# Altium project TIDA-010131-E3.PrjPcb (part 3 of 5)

## Sheet TIDA-010131-E3_LMX2594R_1.SchDoc: LMX2594R
size 431 x 279 mm; Date: Not shown in title block; ApprovedBy: Not shown in title block; CheckedBy: Not shown in title block; Author: Not shown in title block; CompanyName: Not shown in title block; DrawnBy: Avinash N; Engineer: Not shown in title block; Organization: Not shown in title block; Address1: Not shown in title block; Address2: Not shown in title block; Address3: Not shown in title block; Address4: Not shown in title block; DocumentNumber: 1; Revision: Use project parameter SCH_Rev; SheetNumber: 5; SheetTotal: 9; PageSetup: Record=PageOptions¦CenterHorizontal=True¦CenterVertical=True¦PrintScale=1.00¦XCorrection=1.00¦YCorrection=1.00¦PrintKind=0¦BorderSize=5000000¦LeftOffset=0¦BottomOffset=0¦Orientation=2¦PaperLength=1000¦PaperWidth=1000¦Scale=100¦PaperSource=15¦PrintQuality=600¦MediaType=1¦DitherType=10¦PaperKind=Letter¦PrintScaleMode=1
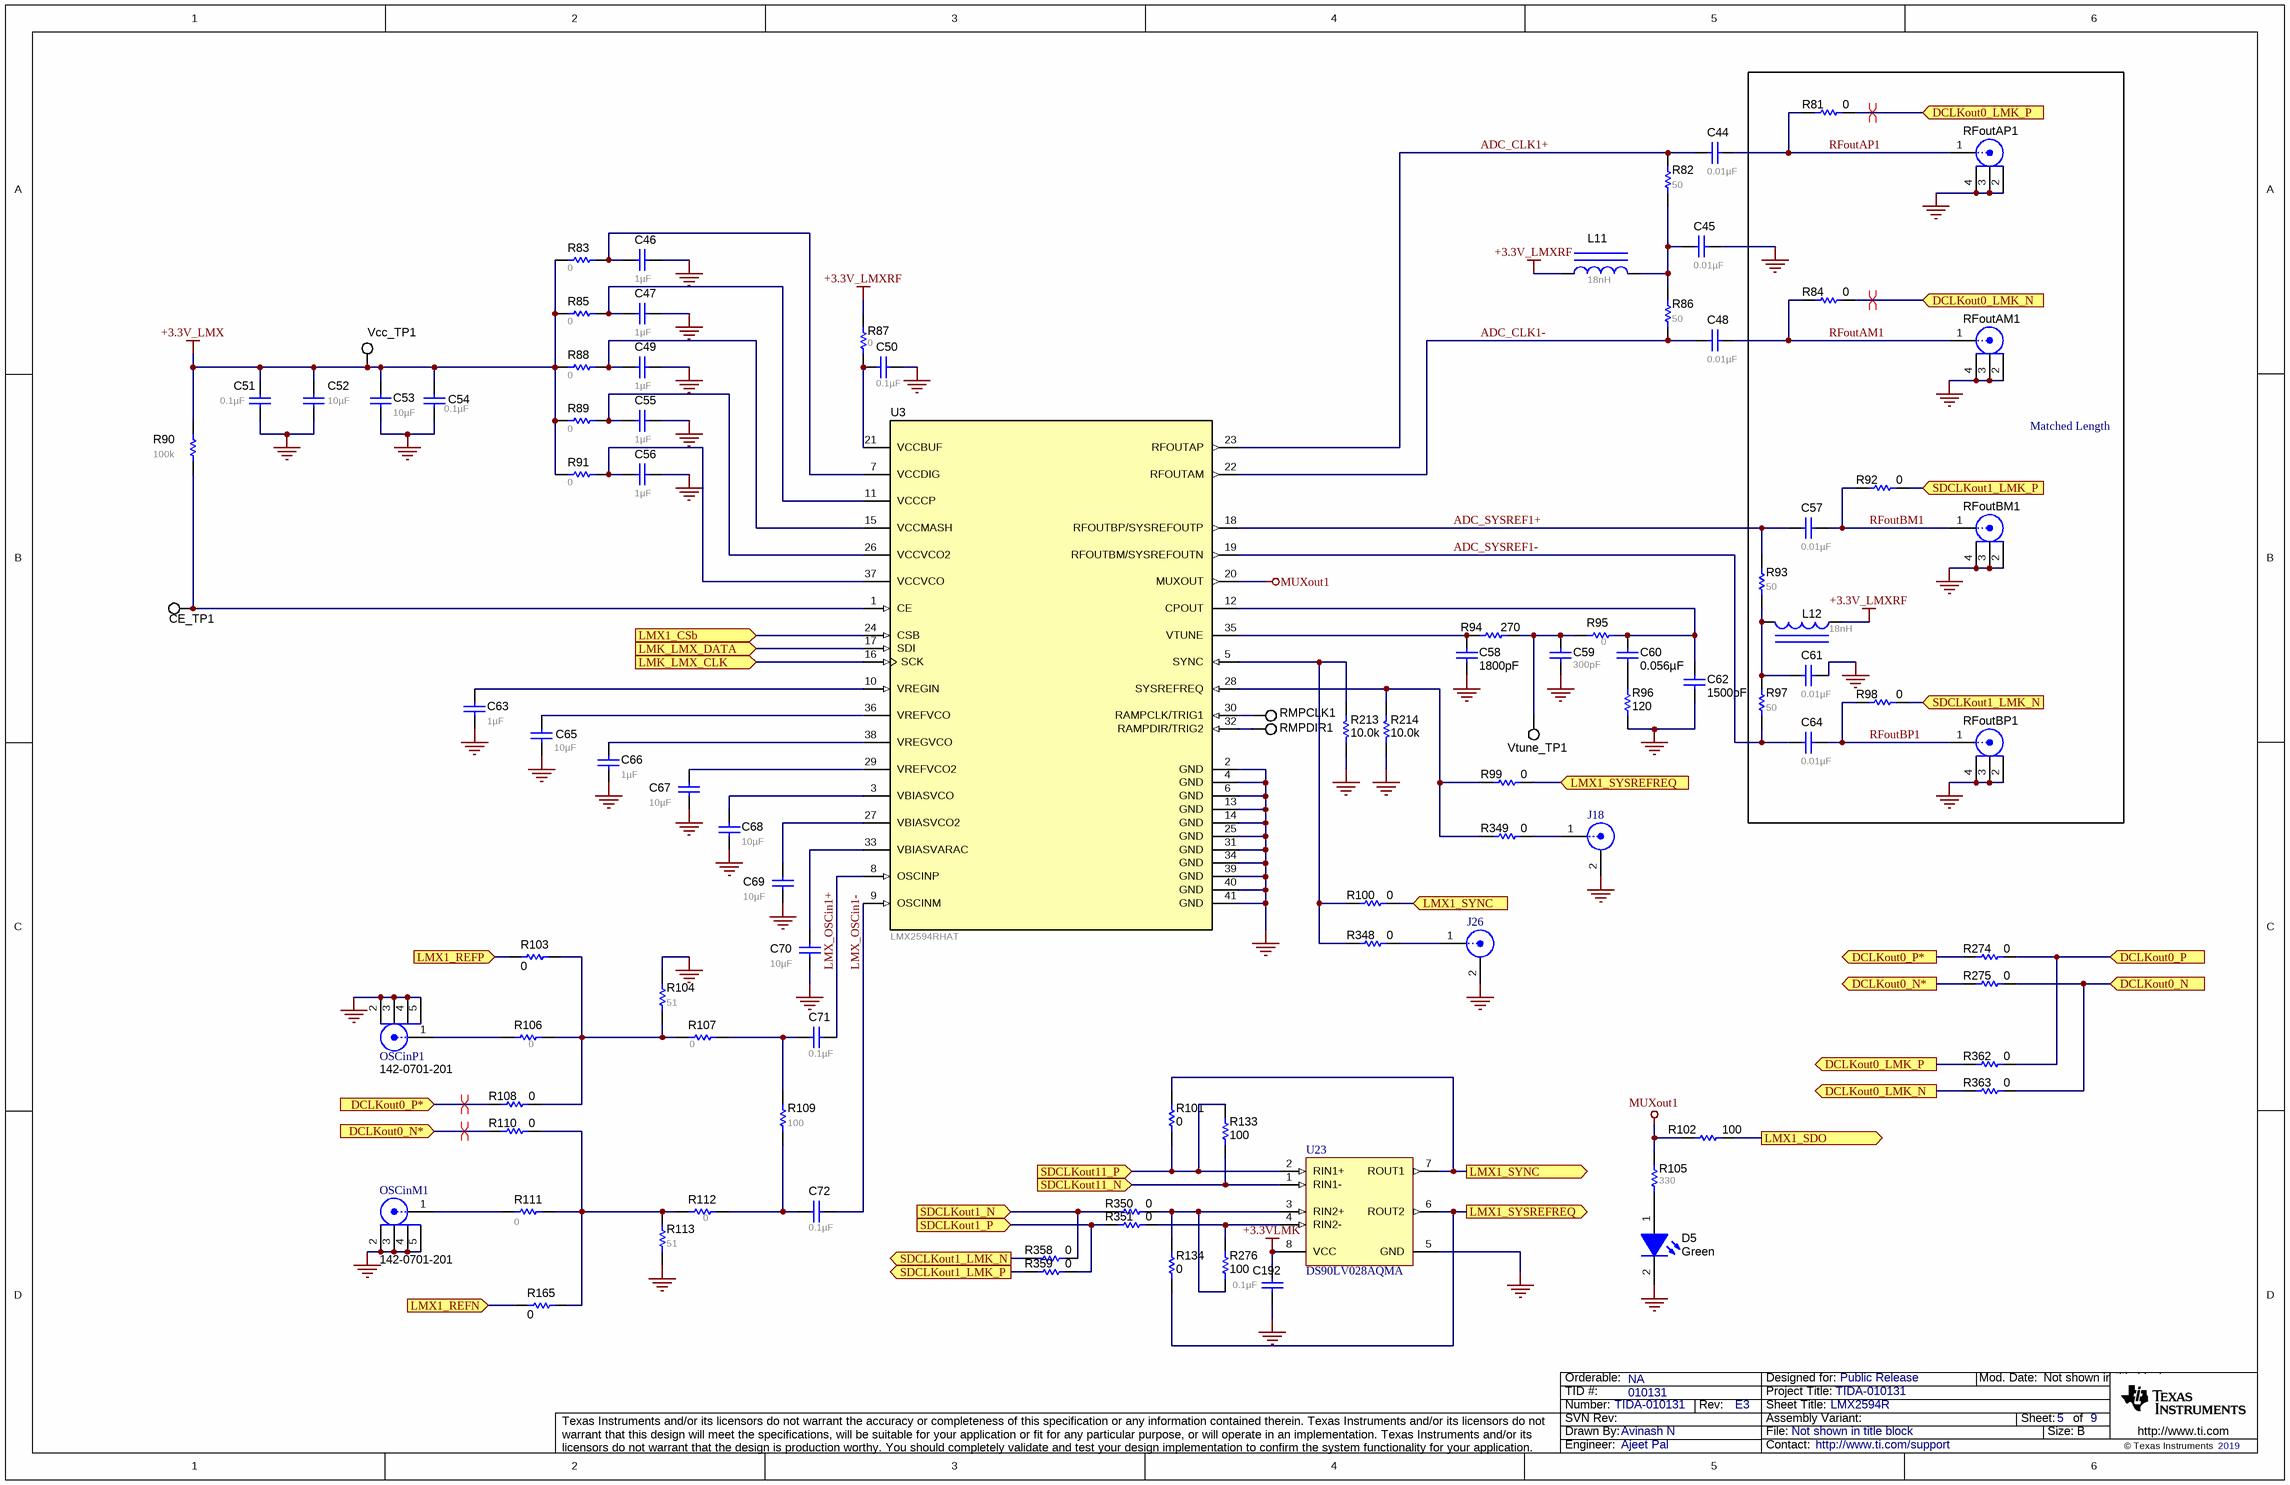
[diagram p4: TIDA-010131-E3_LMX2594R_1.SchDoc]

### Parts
C44  ValueDisplayed: 0.01µF  [0402_065]  (hidden comment: 520L103KT16T)
C45  ValueDisplayed: 0.01µF  [0402_065]  (hidden comment: 520L103KT16T)
C46  ValueDisplayed: 1µF  [0603]  (hidden comment: C1608X7R1C105K080AC)
C47  ValueDisplayed: 1µF  [0603L]  (hidden comment: C1608X7R1C105K080AC)
C48  ValueDisplayed: 0.01µF  [0402_065]  (hidden comment: 520L103KT16T)
C49  ValueDisplayed: 1µF  [0603L]  (hidden comment: C1608X7R1C105K080AC)
C50  ValueDisplayed: 0.1µF  [0603L]  (hidden comment: 0603YC104JAT2A)
C51  ValueDisplayed: 0.1µF  [0603]  (hidden comment: 0603YC104JAT2A)
C52  ValueDisplayed: 10µF  [0805]  (hidden comment: C0805C106K8PACTU)
C53  ValueDisplayed: 10µF  [0805]  (hidden comment: C0805C106K8PACTU)
C54  ValueDisplayed: 0.1µF  [0603]  (hidden comment: 0603YC104JAT2A)
C55  ValueDisplayed: 1µF  [0603]  (hidden comment: C1608X7R1C105K080AC)
C56  ValueDisplayed: 1µF  [0603]  (hidden comment: C1608X7R1C105K080AC)
C57  ValueDisplayed: 0.01µF  [0402_065]  (hidden comment: 520L103KT16T)
C58  ValueDisplayed: 1800pF  [0603]  (hidden comment: GRM1885C1H182JA01D)
C59  ValueDisplayed: 300pF  [0603]  (hidden comment: GRM1885C2A301JA01D)
C60  ValueDisplayed: 0.056µF  [0603]  (hidden comment: GRM188R71H563KA93D)
C61  ValueDisplayed: 0.01µF  [0402_065]  (hidden comment: 520L103KT16T)
C62  ValueDisplayed: 1500pF  [0603]  (hidden comment: GRM1885C1H152JA01J)
C63  ValueDisplayed: 1µF  [0603]  (hidden comment: C1608X7R1C105K080AC)
C64  ValueDisplayed: 0.01µF  [0402_065]  (hidden comment: 520L103KT16T)
C65  ValueDisplayed: 10µF  [0603]  (hidden comment: C1608X5R1A106M080AC)
C66  ValueDisplayed: 1µF  [0603]  (hidden comment: C1608X7R1C105K080AC)
C67  ValueDisplayed: 10µF  [0603]  (hidden comment: C1608X5R1A106M080AC)
C68  ValueDisplayed: 10µF  [0603]  (hidden comment: C1608X5R1A106M080AC)
C69  ValueDisplayed: 10µF  [0603]  (hidden comment: C1608X5R1A106M080AC)
C70  ValueDisplayed: 10µF  [0603]  (hidden comment: C1608X5R1A106M080AC)
C71  ValueDisplayed: 0.1µF  [0603L]  (hidden comment: 0603YC104JAT2A)
C72  ValueDisplayed: 0.1µF  [0603L]  (hidden comment: 0603YC104JAT2A)
C192  ValueDisplayed: 0.1µF  [0603]  (hidden comment: 0603YC104JAT2A)
CE_TP1  5007  [Keystone5007]  (value not drawn)
D5  value Green  [LTST-C191_Green]  (hidden comment: LTST-C191TGKT)
J18  (no value)  [Molex_0853050232]
J26  (no value)  [Molex_0853050232]
L11  ValueDisplayed: 18nH  [IND_LQG15H]  (hidden comment: LQG15HS18NJ02D)
L12  ValueDisplayed: 18nH  [IND_LQG15H]  (hidden comment: LQG15HS18NJ02D)
OSCinM1  142-0701-201  [Johnson_142-0701-20x]
OSCinP1  142-0701-201  [Johnson_142-0701-20x]
R81  ValueDisplayed: 0  [0402]  (hidden comment: CRCW04020000Z0ED)
R82  ValueDisplayed: 50  [0402L]  (hidden comment: FC0402E50R0BST1)
R83  value 0  [0603]  (hidden comment: CRCW06030000Z0EA)
R84  ValueDisplayed: 0  [0402]  (hidden comment: CRCW04020000Z0ED)
R85  value 0  [0603L]  (hidden comment: CRCW06030000Z0EA)
R86  ValueDisplayed: 50  [0402L]  (hidden comment: FC0402E50R0BST1)
R87  value 0  [0603L]  (hidden comment: CRCW06030000Z0EA)
R88  value 0  [0603L]  (hidden comment: CRCW06030000Z0EA)
R89  value 0  [0603]  (hidden comment: CRCW06030000Z0EA)
R90  ValueDisplayed: 100k  [0603]  (hidden comment: CRCW0603100KJNEA)
R91  value 0  [0603]  (hidden comment: CRCW06030000Z0EA)
R92  ValueDisplayed: 0  [0402]  (hidden comment: CRCW04020000Z0ED)
R93  ValueDisplayed: 50  [0402L]  (hidden comment: FC0402E50R0BST1)
R94  ValueDisplayed: 270  [0603]  (hidden comment: RC0603JR-07270RL)
R95  ValueDisplayed: 0  [0603]  (hidden comment: CRCW06030000Z0EA)
R96  ValueDisplayed: 120  [0603]  (hidden comment: CRCW0603120RJNEA)
R97  ValueDisplayed: 50  [0402L]  (hidden comment: FC0402E50R0BST1)
R98  ValueDisplayed: 0  [0402]  (hidden comment: CRCW04020000Z0ED)
R99  ValueDisplayed: 0  [0402]  (hidden comment: CRCW04020000Z0ED)
R100  ValueDisplayed: 0  [0402]  (hidden comment: CRCW04020000Z0ED)
R101  ValueDisplayed: 0  [0402]  (hidden comment: CRCW04020000Z0ED)
R102  ValueDisplayed: 100  [0603]  (hidden comment: CRCW0603100RFKEA)
R103  ValueDisplayed: 0  [0402]  (hidden comment: CRCW04020000Z0ED)
R104  ValueDisplayed: 51  [0603]  (hidden comment: CRCW060351R0JNEA)
R105  value 330  [0603]  (hidden comment: RC0603JR-07330RL)
R106  ValueDisplayed: 0  [0603]  (hidden comment: CRCW06030000Z0EA)
R107  ValueDisplayed: 0  [0603]  (hidden comment: CRCW06030000Z0EA)
R108  ValueDisplayed: 0  [0402]  (hidden comment: CRCW04020000Z0ED)
R109  ValueDisplayed: 100  [0603L]  (hidden comment: CRCW0603100RFKEA)
R110  ValueDisplayed: 0  [0402]  (hidden comment: CRCW04020000Z0ED)
R111  ValueDisplayed: 0  [0603]  (hidden comment: CRCW06030000Z0EA)
R112  ValueDisplayed: 0  [0603]  (hidden comment: CRCW06030000Z0EA)
R113  ValueDisplayed: 51  [0603]  (hidden comment: CRCW060351R0JNEA)
R133  ValueDisplayed: 100  [0402]  (hidden comment: CRCW0402100RJNED)
R134  ValueDisplayed: 0  [0402]  (hidden comment: CRCW04020000Z0ED)
R165  ValueDisplayed: 0  [0402]  (hidden comment: CRCW04020000Z0ED)
R213  ValueDisplayed: 10.0k  [0402]  (hidden comment: CRCW040210K0DHEDP)
R214  ValueDisplayed: 10.0k  [0402]  (hidden comment: CRCW040210K0DHEDP)
R274  ValueDisplayed: 0  [0402]  (hidden comment: CRCW04020000Z0ED)
R275  ValueDisplayed: 0  [0402]  (hidden comment: CRCW04020000Z0ED)
R276  ValueDisplayed: 100  [0402]  (hidden comment: CRCW0402100RJNED)
R348  ValueDisplayed: 0  [0402]  (hidden comment: CRCW04020000Z0ED)
R349  ValueDisplayed: 0  [0402]  (hidden comment: CRCW04020000Z0ED)
R350  ValueDisplayed: 0  [0402]  (hidden comment: CRCW04020000Z0ED)
R351  ValueDisplayed: 0  [0402]  (hidden comment: CRCW04020000Z0ED)
R358  ValueDisplayed: 0  [0402]  (hidden comment: CRCW04020000Z0ED)
R359  ValueDisplayed: 0  [0402]  (hidden comment: CRCW04020000Z0ED)
R362  ValueDisplayed: 0  [0402]  (hidden comment: CRCW04020000Z0ED)
R363  ValueDisplayed: 0  [0402]  (hidden comment: CRCW04020000Z0ED)
RFoutAM1  142-0771-831  [Johnson_142-0771-831]  (value not drawn)
RFoutAP1  142-0771-831  [Johnson_142-0771-831]  (value not drawn)
RFoutBM1  142-0771-831  [Johnson_142-0771-831]  (value not drawn)
RFoutBP1  142-0771-831  [Johnson_142-0771-831]  (value not drawn)
RMPCLK1  5007  [Keystone5007]  (value not drawn)
RMPDIR1  5007  [Keystone5007]  (value not drawn)
U3  LMX2594RHAT  [RHA0040A]
U23  DS90LV028AQMA  [M08A_N]
Vcc_TP1  5007  [Keystone5007]  (value not drawn)
Vtune_TP1  5007  [Keystone5007]  (value not drawn)

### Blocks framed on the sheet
Matched Length: C57 C61 C64 L12 R81 R84 R92 R93 R97 R98 RFoutAM1 RFoutAP1 RFoutBM1 RFoutBP1

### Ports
DCLKout0_LMK_N (in), DCLKout0_LMK_N (out), DCLKout0_LMK_P (in), DCLKout0_LMK_P (out), DCLKout0_N (in), DCLKout0_N* (in), DCLKout0_N* (out), DCLKout0_P (in), DCLKout0_P* (in), DCLKout0_P* (out), LMK_LMX_CLK (in), LMK_LMX_DATA (in), LMX1_CSb (in), LMX1_REFN (in), LMX1_REFP (in), LMX1_SDO (out), LMX1_SYNC (in), LMX1_SYNC (out), LMX1_SYSREFREQ (in), LMX1_SYSREFREQ (out), SDCLKout1_LMK_N (in), SDCLKout1_LMK_N (out), SDCLKout1_LMK_P (in), SDCLKout1_LMK_P (out), SDCLKout1_N (in), SDCLKout1_P (in), SDCLKout11_N (in), SDCLKout11_P (in)

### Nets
+3.3V_LMX: C51.2 C52.2 C53.2 C54.2 R83.1 R85.1 R88.1 R89.2 R90.1 R91.2 Vcc_TP1.1
+3.3V_LMXRF: L11.1 L12.1 R87.1
+3.3VLMK: C192.2 U23.8(VCC)
GND: C45.1 C46.1 C47.1 C49.2 C50.1 C51.1 C52.1 C53.1 C54.1 C55.1 C56.1 C58.1 C59.2 C61.1 C62.2 C63.1 C65.2 C66.1 C67.2 C68.2 C69.1 C70.1 C192.1 D5.2(K) J18.2 J26.2 OSCinM1.2 OSCinM1.3 OSCinM1.4 OSCinM1.5 OSCinP1.2 OSCinP1.3 OSCinP1.4 OSCinP1.5 R96.2 R104.2 R113.1 R213.2 R214.2 RFoutAM1.2 RFoutAM1.3 RFoutAM1.4 RFoutAP1.2 RFoutAP1.3 RFoutAP1.4 RFoutBM1.2 RFoutBM1.3 RFoutBM1.4 RFoutBP1.2 RFoutBP1.3 RFoutBP1.4 U3.2(GND) U3.4(GND) U3.6(GND) U3.13(GND) U3.14(GND) U3.25(GND) U3.31(GND) U3.34(GND) U3.39(GND) U3.40(GND) U3.41(GND) U23.5(GND)
MUXout1: R102.1 R105.2 U3.20(MUXOUT)
ADC_CLK1+: C44.2 R82.1 U3.23(RFOUTAP)
ADC_CLK1-: C48.2 R86.1 U3.22(RFOUTAM)
ADC_SYSREF1+: C57.2 R93.2 U3.18(RFOUTBP/SYSREFOUTP)
ADC_SYSREF1-: C64.2 R97.1 U3.19(RFOUTBM/SYSREFOUTN)
DCLKout0_LMK_N: R84.2 R363.1 ; port DCLKout0_LMK_N
DCLKout0_LMK_P: R81.2 R362.1 ; port DCLKout0_LMK_P
DCLKout0_N: R275.2 R363.2 ; port DCLKout0_N
DCLKout0_N*: R110.1 R275.1 ; port DCLKout0_N*
DCLKout0_P: R274.2 R362.2 ; port DCLKout0_P
DCLKout0_P*: R108.1 R274.1 ; port DCLKout0_P*
LMK_LMX_CLK: U3.16(SCK) ; port LMK_LMX_CLK
LMK_LMX_DATA: U3.17(SDI) ; port LMK_LMX_DATA
LMX1_CSb: U3.24(CSB) ; port LMX1_CSb
LMX1_REFN: R165.1 ; port LMX1_REFN
LMX1_REFP: R103.2 ; port LMX1_REFP
LMX1_SDO: R102.2 ; port LMX1_SDO
LMX1_SYNC: R100.2 R101.1 U23.7(ROUT1) ; port LMX1_SYNC
LMX1_SYSREFREQ: R99.2 R134.2 U23.6(ROUT2) ; port LMX1_SYSREFREQ
LMX_OSCin1+: C71.2 U3.8(OSCINP)
LMX_OSCin1-: C72.2 U3.9(OSCINM)
RFoutAM1: C48.1 R84.1 RFoutAM1.1
RFoutAP1: C44.1 R81.1 RFoutAP1.1
RFoutBM1: C57.1 R92.1 RFoutBM1.1
RFoutBP1: C64.1 R98.1 RFoutBP1.1
SDCLKout1_LMK_N: R98.2 R358.1 ; port SDCLKout1_LMK_N
SDCLKout1_LMK_P: R92.2 R359.1 ; port SDCLKout1_LMK_P
SDCLKout1_N: R350.1 R358.2 ; port SDCLKout1_N
SDCLKout1_P: R351.1 R359.2 ; port SDCLKout1_P
SDCLKout11_N: R133.1 U23.1(RIN1-) ; port SDCLKout11_N
SDCLKout11_P: R101.2 R133.2 U23.2(RIN1+) ; port SDCLKout11_P
NetC45_2: C45.2 L11.2 R82.2 R86.2
NetC46_2: C46.2 R83.2 U3.7(VCCDIG)
NetC47_2: C47.2 R85.2 U3.11(VCCCP)
NetC49_1: C49.1 R88.2 U3.15(VCCMASH)
NetC50_2: C50.2 R87.2 U3.21(VCCBUF)
NetC55_2: C55.2 R89.1 U3.26(VCCVCO2)
NetC56_2: C56.2 R91.1 U3.37(VCCVCO)
NetC58_2: C58.2 R94.1 U3.35(VTUNE)
NetC59_1: C59.1 R94.2 R95.2 Vtune_TP1.1
NetC60_1: C60.1 C62.1 R95.1 U3.12(CPOUT)
NetC60_2: C60.2 R96.1
NetC61_2: C61.2 L12.2 R93.1 R97.2
NetC63_2: C63.2 U3.10(VREGIN)
NetC65_1: C65.1 U3.36(VREFVCO)
NetC66_2: C66.2 U3.38(VREGVCO)
NetC67_1: C67.1 U3.29(VREFVCO2)
NetC68_1: C68.1 U3.3(VBIASVCO)
NetC69_2: C69.2 U3.27(VBIASVCO2)
NetC70_2: C70.2 U3.33(VBIASVARAC)
NetC71_1: C71.1 R107.2 R109.2
NetC72_1: C72.1 R109.1 R112.1
NetCE_TP1_1: CE_TP1.1 R90.2 U3.1(CE)
NetD5_1: D5.1(A) R105.1
NetJ18_1: J18.1 R349.2
NetJ26_1: J26.1 R348.2
NetOSCinM1_1: OSCinM1.1 R111.1
NetOSCinP1_1: OSCinP1.1 R106.1
NetR99_1: R99.1 R214.1 R349.1 U3.28(SYSREFREQ)
NetR100_1: R100.1 R213.1 R348.1 U3.5(SYNC)
NetR103_1: R103.1 R104.1 R106.2 R107.1 R108.2
NetR110_2: R110.2 R111.2 R112.2 R113.2 R165.2
NetR134_1: R134.1 R276.1 R350.2 U23.3(RIN2+)
NetR276_2: R276.2 R351.2 U23.4(RIN2-)
NetRMPCLK1_1: RMPCLK1.1 U3.30(RAMPCLK/TRIG1)
NetRMPDIR1_1: RMPDIR1.1 U3.32(RAMPDIR/TRIG2)

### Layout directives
differential pair: DCLKout0_LMK_N, DCLKout0_LMK_P, DCLKout0_N*, DCLKout0_P*

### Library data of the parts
C44 C45 C48 C57 C61 C64 = 520L103KT16T: CAP, CERM, 0.01 µF, 16 V, +/- 10%, X7R, 0402; Manufacturer: AT Ceramics; Polarized: N; CompType: Capacitor; Value: 0.01uF; U/M: EA; Cap_F: 0.00000001; Tolerance_%: 10; Value1: Unknown; VDC_V: 16; Value2: 16V; TaMin_C: -55; TaMax_C: 125; Cap_Case: 0402; AEC Category: Q200; SizeArea_mm2: 0.5; SizeAreaWB_mm2: 3; SizeX_mm: 1; SizeZ_mm: 0.65
C46 C55 C56 = C1608X7R1C105K080AC: CAP, CERM, 1 µF, 16 V, +/- 10%, X7R, 0603; Manufacturer: TDK; ESR_ohm: 0.0057; Polarized: N; TaMax_C: 125; TaMin_C: -55; Tolerance_%: 10; VDC_V: 16; Cap_F: 0.000001; CompType: Capacitor; Value: 1uF; Value1: 0.0057 ohm; Value2: 16V; U/M: EA; SizeArea_mm2: 1.28; SizeAreaWB_mm2: 4.68; SizeX_mm: 1.6; SizeY_mm: 0.8; SizeZ_mm: 1; AEC Category: Q200
C47 C49 = C1608X7R1C105K080AC: CAP, CERM, 1 µF, 16 V, +/- 10%, X7R, 0603; Manufacturer: TDK; Cap_Case: 0603; ESR_ohm: 0.0057; Polarized: N; TaMax_C: 125; TaMin_C: -55; Tolerance_%: 10; VDC_V: 16; Cap_F: 0.000001; CompType: Capacitor; Value: 1uF; Value1: 0.0057 ohm; Value2: 16V; U/M: EA; SizeArea_mm2: 1.28; SizeAreaWB_mm2: 4.68; SizeX_mm: 1.6; SizeY_mm: 0.8; SizeZ_mm: 1; AEC Category: Q200
C50 C71 C72 = 0603YC104JAT2A: CAP, CERM, 0.1uF, 16V, +/-5%, X7R, 0603; Manufacturer: AVX; Cap_Case: 0603; ESR_Ohm: 0.039; Polarized: N; TaMax_C: 125; TaMin_C: -55; Tolerance_%: 5; VDC_V: 16; Cap_F: 0.0000001; CompType: Capacitor; Value1: 0.039 ohm; U/M: EA
C51 C54 C192 = 0603YC104JAT2A: CAP, CERM, 0.1uF, 16V, +/-5%, X7R, 0603; Manufacturer: AVX; ESR_Ohm: 0.039; Polarized: N; TaMax_C: 125; TaMin_C: -55; Tolerance_%: 5; VDC_V: 16; Cap_F: 0.0000001; CompType: Capacitor; Value1: 0.039 ohm; U/M: EA
C52 C53 = C0805C106K8PACTU: CAP, CERM, 10uF, 10V, +/-10%, X5R, 0805; Manufacturer: Kemet; ESR_Ohm: 0.003; IRMS_A: 11.43; Polarized: N; TaMax_C: 85; TaMin_C: -55; Tolerance_%: 10; Cap_F: 0.00001; CompType: Capacitor; U/M: EA; Value1: 0.003 ohm
C58 = GRM1885C1H182JA01D: CAP, CERM, 1800 pF, 50 V,+/- 5%, C0G/NP0, 0603; Manufacturer: MuRata; Polarized: N; TaMax_C: 125; TaMin_C: -55; Tolerance_%: 5; VDC_V: 50; Cap_F: 0.0000000018; CompType: Capacitor; Value: 1800pF; Value2: 50V; U/M: EA; SizeArea_mm2: 1.28; SizeAreaWB_mm2: 4.68; SizeX_mm: 1.6; SizeY_mm: 0.8; SizeZ_mm: 1; AEC Category: Q200
C59 = GRM1885C2A301JA01D: CAP, CERM, 300pF, 100V, +/-5%, C0G/NP0, 0603; Manufacturer: MuRata; Polarized: N; TaMax_C: 125; TaMin_C: -55; Tolerance_%: 5; VDC_V: 100; Cap_F: 0.0000000003; CompType: Capacitor; Value1: Unknown; U/M: EA
C60 = GRM188R71H563KA93D: CAP, CERM, 0.056 µF, 50 V,+/- 10%, X7R, 0603; Manufacturer: MuRata; Polarized: N; TaMax_C: 125; TaMin_C: -55; Tolerance_%: 10; VDC_V: 50; Cap_F: 0.000000056; CompType: Capacitor; Value: 0.056uF; Value2: 50V; U/M: EA; AEC Category: Q200; SizeArea_mm2: 1.28; SizeAreaWB_mm2: 4.68; SizeX_mm: 1.6; SizeY_mm: 0.8; SizeZ_mm: 1; Green_Lifecycle: Active; Green_REACh: Passed
C62 = GRM1885C1H152JA01J: CAP, CERM, 1500 pF, 50 V,+/- 5%, C0G/NP0, 0603; Manufacturer: MuRata; Polarized: N; TaMax_C: 125; TaMin_C: -55; Tolerance_%: 5; VDC_V: 50; Cap_F: 0.0000000015; CompType: Capacitor; Value: 1500pF; Value2: 50V; U/M: EA; AEC Category: Q200; SizeArea_mm2: 1.28; SizeAreaWB_mm2: 4.68; SizeX_mm: 1.6; SizeY_mm: 0.8; SizeZ_mm: 1
C63 = C1608X7R1C105K080AC: CAP, CERM, 1 µF, 16 V, +/- 10%, X7R, 0603; Manufacturer: TDK; Polarized: N; CompType: Capacitor; Value: 1uF; U/M: EA; Cap_F: 0.000001; Tolerance_%: 10; ESR_ohm: 0.0057; Value1: 0.0057 ohm; VDC_V: 16; Value2: 16V; TaMin_C: -55; TaMax_C: 125; AEC Category: Q200
C65 C67-C70 = C1608X5R1A106M080AC: CAP, CERM, 10 µF, 10 V, +/- 20%, X5R, 0603; Manufacturer: TDK; ESR_ohm: 0.0078; IRMS_A: 1.85; Polarized: N; TaMax_C: 85; TaMin_C: -55; Tolerance_%: 20; VDC_V: 10; Cap_F: 0.00001; CompType: Capacitor; Value: 10uF; U/M: EA; Value1: 0.0078 ohm; Value2: 10V; AEC Category: Q200
C66 = C1608X7R1C105K080AC: CAP, CERM, 1 µF, 16 V, +/- 10%, X7R, 0603; Manufacturer: TDK; ESR_ohm: 0.0057; Polarized: N; TaMax_C: 125; TaMin_C: -55; Tolerance_%: 10; VDC_V: 16; Cap_F: 0.000001; CompType: Capacitor; Value: 1uF; U/M: EA; Value1: 0.0057 ohm; Value2: 16V; AEC Category: Q200
CE_TP1 RMPCLK1 RMPDIR1 Vcc_TP1 Vtune_TP1 = 5007: Test Point, Compact, White, TH; Manufacturer: Keystone; CompType: Test Point Loop; U/M: EA
D5 = LTST-C191TGKT: LED, Green, SMD; Manufacturer: Lite-On; Type: InGaN; Vf_V: 3.2; Value2: 3.2V; Io_A: 0.02; Value1: W; U/M: EA
J18 J26 = CMP-0077224-1: Plug, 50 Ohm, Straight, SMT; PartNumber: 0853050232; Manufacturer: Molex; Cert_UL: Y; ContactFinish: Gold; CT: False; Gender: Male; Voltage_V: 335V
L11 L12 = LQG15HS18NJ02D: Inductor, Multilayer, Air Core, 18 nH, 0.3 A, 0.36 ohm, SMD; Manufacturer: MuRata; Value: 18nH; Ind_H: 18.0E-9; Imax_A: 0.3; Irms: 0.3A @ C rise; Isat: 0.3A @ % inductance drop; DCR_ohm: 0.36; Value2: 0.3A; AEC Category: Q200
OSCinM1 OSCinP1 = 142-0701-201: Connector, TH, SMA; Manufacturer: Emerson Network Power; SymbolCreator: X0208326
R81 R84 R92 R98-R101 R108 R110 R134 R274 R275 R348-R351 R358 R359 R362 R363 = CRCW04020000Z0ED: RES, 0, 5%, 0.063 W, 0402; Manufacturer: Vishay-Dale; CompType: Resistor; Value: 0; Value_Code: 0000; Tolerance_%: 5; Power_W: 0.063; Value2: 0.063W; VDC_V: 50; TempCo: 200 ppm/C; SizeArea_mm2: 0.5; SizeX_mm: 1; SizeZ_mm: 0.6; EIA_Code: E24; U/M: EA; AEC Category: Q200
R82 R86 R93 R97 = FC0402E50R0BST1: RES, 50, 0.1%, 0.05 W, 0402; Manufacturer: Vishay-Dale; CompType: Resistor; Value: 50; Value_Code: 50R0; Tolerance_%: 0.1; Power_W: 0.05; Value2: 0.05W; TempCo: 25 ppm/C; U/M: EA; SizeArea_mm2: 0.5; SizeX_mm: 1; SizeZ_mm: 0.6; AEC Category: Q200; AEC Qualified: N
R83 R85 R87-R89 R91 = CRCW06030000Z0EA: RES, 0 ohm, 5%, 0.1W, 0603; Manufacturer: Vishay-Dale; CompType: Resistor; Tolerance_%: 5; VDC_V: 75; Power_W: 0.1; U/M: EA; Value_Code: 0000; EIA_Code: E24
R90 = CRCW0603100KJNEA: RES, 100 k, 5%, 0.1 W, 0603; Manufacturer: Vishay-Dale; CompType: Resistor; Tolerance_%: 5; VDC_V: 75; Power_W: 0.1; Res_ohm: 100000; Value: 100k; U/M: EA; Value2: 0.1W; EIA_Code: E24; TempCo: 200 ppm/C; SizeArea_mm2: 1.28; SizeX_mm: 1.6; SizeY_mm: 0.8; SizeZ_mm: 1; AEC Category: Q200
R94 = RC0603JR-07270RL: RES, 270, 5%, 0.1 W, 0603; Manufacturer: Yageo America; CompType: Resistor; Tolerance_%: 5; VDC_V: 50; Power_W: 0.1; Value: 270; U/M: EA; Value_Code: 270R; Value2: 0.1W; EIA_Code: E24; TempCo: 100 ppm/C; SizeArea_mm2: 1.28; SizeX_mm: 1.6; SizeY_mm: 0.8; SizeZ_mm: 1; AEC Category: Q200
R95 R106 R107 R111 R112 = CRCW06030000Z0EA: RES, 0, 5%, 0.1 W, 0603; Manufacturer: Vishay-Dale; CompType: Resistor; Tolerance_%: 5; VDC_V: 75; Power_W: 0.1; Value: 0; U/M: EA; Value_Code: 0000; Value2: 0.1W; EIA_Code: E24; TempCo: 200 ppm/C; SizeArea_mm2: 1.28; SizeX_mm: 1.6; SizeY_mm: 0.8; SizeZ_mm: 1; AEC Category: Q200
R96 = CRCW0603120RJNEA: RES, 120, 5%, 0.1 W, 0603; Manufacturer: Vishay-Dale; CompType: Resistor; Tolerance_%: 5; VDC_V: 75; Power_W: 0.1; Value: 120; U/M: EA; Value_Code: 120R; Value2: 0.1W; TempCo: 200 ppm/C; EIA_Code: E24; SizeArea_mm2: 1.28; SizeX_mm: 1.6; SizeY_mm: 0.8; SizeZ_mm: 1; AEC Category: Q200; Green_Lifecycle: Active; Green_REACh: Passed
R102 = CRCW0603100RFKEA: RES, 100, 1%, 0.1 W, 0603; Manufacturer: Vishay-Dale; CompType: Resistor; Value: 100; Value_Code: 100R; Tolerance_%: 1; Power_W: 0.1; Value2: 0.1W; VDC_V: 75; TempCo: 100 ppm/C; SizeArea_mm2: 1.28; SizeX_mm: 1.6; SizeY_mm: 0.8; EIA_Code: E96; U/M: EA; AEC Category: Q200
R103 R165 = CRCW04020000Z0ED: RES, 0, 5%, 0.063 W, 0402; Manufacturer: Vishay-Dale; CompType: Resistor; Tolerance_%: 5; VDC_V: 50; Power_W: 0.063; Value: 0; U/M: EA; Value_Code: 0000; Value2: 0.063W; EIA_Code: E24; TempCo: 200 ppm/C; SizeArea_mm2: 0.5; SizeX_mm: 1; SizeZ_mm: 0.6; AEC Category: Q200
R104 R113 = CRCW060351R0JNEA: RES, 51, 5%, 0.1 W, 0603; Manufacturer: Vishay-Dale; CompType: Resistor; Value: 51; Value_Code: 51R0; Tolerance_%: 5; Power_W: 0.1; Value2: 0.1W; VDC_V: 75; TempCo: 200 ppm/C; EIA_Code: E24; U/M: EA; SizeArea_mm2: 1.28; SizeX_mm: 1.6; SizeY_mm: 0.8; SizeZ_mm: 1; AEC Category: Q200
R105 = RC0603JR-07330RL: RES, 330 ohm, 5%, 0.1W, 0603; Manufacturer: Yageo America; CompType: Resistor; Tolerance_%: 5; VDC_V: 50; Power_W: 0.1; U/M: EA; Value_Code: 330R; EIA_Code: E24
R109 = CRCW0603100RFKEA: RES, 100, 1%, 0.1 W, 0603; Manufacturer: Vishay-Dale; CompType: Resistor; Tolerance_%: 1; VDC_V: 75; Power_W: 0.1; Value: 100; U/M: EA; Value_Code: 100R; Value2: 0.1W; EIA_Code: E96; TempCo: 100 ppm/C; SizeArea_mm2: 1.28; SizeX_mm: 1.6; SizeY_mm: 0.8; AEC Category: Q200
R133 R276 = CRCW0402100RJNED: RES, 100, 5%, 0.063 W, 0402; Manufacturer: Vishay-Dale; CompType: Resistor; Value: 100; Value_Code: 100R; Tolerance_%: 5; Power_W: 0.063; Value2: 0.063W; VDC_V: 50; TempCo: 200 ppm/C; SizeArea_mm2: 0.5; SizeX_mm: 1; SizeZ_mm: 0.6; EIA_Code: E24; U/M: EA; AEC Category: Q200
R213 R214 = CRCW040210K0DHEDP: RES, 10.0 k, 0.5%, 0.063 W, 0402; Manufacturer: Vishay-Dale; CompType: Resistor; Value: 10.0k; Res_ohm: 10000; Value_Code: 10k0; Tolerance_%: 0.5; Power_W: 0.063; Value2: 0.063W; VDC_V: 50; TempCo: 50 ppm/C; SizeX_mm: 1; SizeZ_mm: 0.6; EIA_Code: E192; U/M: EA; AEC Category: Q200
RFoutAM1 RFoutAP1 RFoutBM1 RFoutBP1 = 142-0771-831: JACK, SMA, 50 Ohm, Gold, Edge Mount; Manufacturer: Johnson; SymbolCreator: Altium; Gender: Female; Voltage_V: 170
U3 = LMX2594RHAR: High Performance, Wideband PLLatinum RF Synthesizer, RHA0040A (VQFN-40); Manufacturer: Texas Instruments; SymbolCreator: Altium; SizeArea_mm2: 36; SizeAreaWB_mm2: 64; SizeX_mm: 6; SizeZ_mm: 1; CompType: IC; U/M: EA
U23 = DS90LV028AQMA: Automotive LVDS Dual Differential Line Receiver, 8-pin Narrow SOIC; Manufacturer: Texas Instruments; PackageTopMarking: NSZXTT*90LV0*28AQM; PowerWise: N; CompType: Interface IC

## Sheet TIDA-010131-E3_LMX2594R_2.SchDoc: LMX2594R
size 431 x 279 mm; Date: Not shown in title block; ApprovedBy: Not shown in title block; CheckedBy: Not shown in title block; Author: Not shown in title block; CompanyName: Not shown in title block; DrawnBy: Avinash N; Engineer: Not shown in title block; Organization: Not shown in title block; Address1: Not shown in title block; Address2: Not shown in title block; Address3: Not shown in title block; Address4: Not shown in title block; DocumentNumber: 1; Revision: Use project parameter SCH_Rev; SheetNumber: 6; SheetTotal: 9; PageSetup: Record=PageOptions¦CenterHorizontal=True¦CenterVertical=True¦PrintScale=0.59¦XCorrection=1.00¦YCorrection=1.00¦PrintKind=0¦BorderSize=5000000¦LeftOffset=0¦BottomOffset=0¦Orientation=2¦PaperLength=1000¦PaperWidth=1000¦Scale=100¦PaperSource=15¦PrintQuality=600¦MediaType=1¦DitherType=10¦PrintScaleMode=1¦PaperKind=Letter
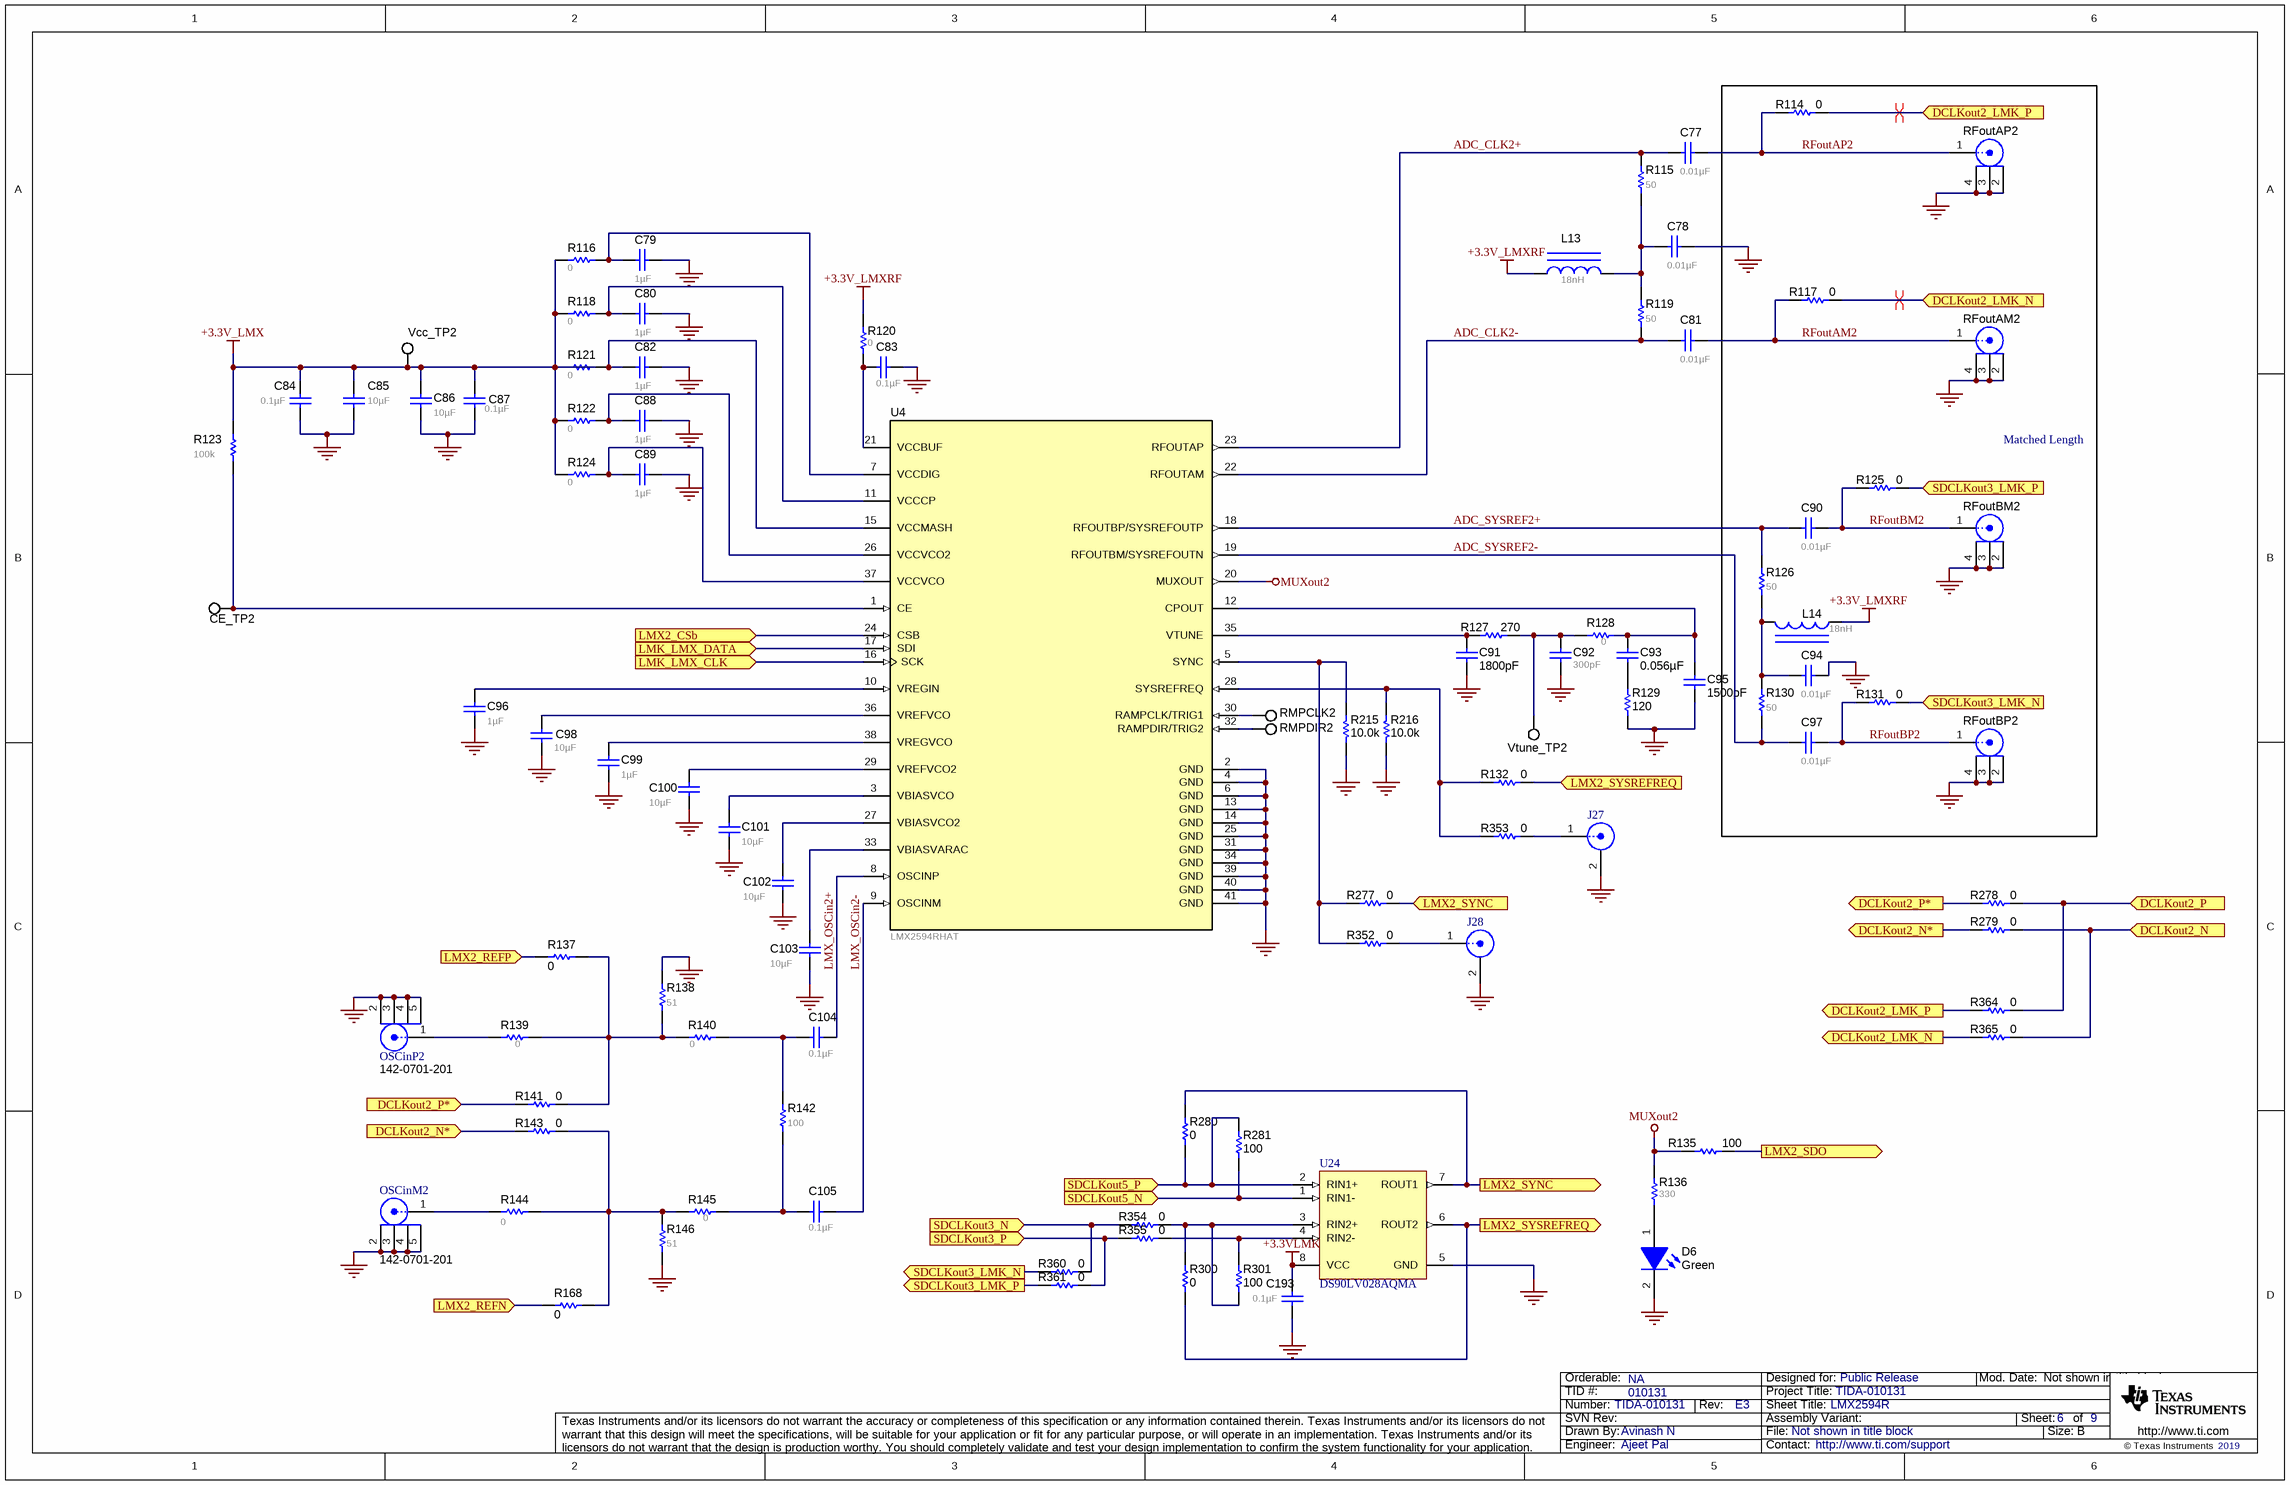
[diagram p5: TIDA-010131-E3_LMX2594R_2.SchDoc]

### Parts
C77  ValueDisplayed: 0.01µF  [0402_065]  (hidden comment: 520L103KT16T)
C78  ValueDisplayed: 0.01µF  [0402_065]  (hidden comment: 520L103KT16T)
C79  ValueDisplayed: 1µF  [0603]  (hidden comment: C1608X7R1C105K080AC)
C80  ValueDisplayed: 1µF  [0603L]  (hidden comment: C1608X7R1C105K080AC)
C81  ValueDisplayed: 0.01µF  [0402_065]  (hidden comment: 520L103KT16T)
C82  ValueDisplayed: 1µF  [0603L]  (hidden comment: C1608X7R1C105K080AC)
C83  ValueDisplayed: 0.1µF  [0603L]  (hidden comment: 0603YC104JAT2A)
C84  ValueDisplayed: 0.1µF  [0603]  (hidden comment: 0603YC104JAT2A)
C85  ValueDisplayed: 10µF  [0805]  (hidden comment: C0805C106K8PACTU)
C86  ValueDisplayed: 10µF  [0805]  (hidden comment: C0805C106K8PACTU)
C87  ValueDisplayed: 0.1µF  [0603]  (hidden comment: 0603YC104JAT2A)
C88  ValueDisplayed: 1µF  [0603]  (hidden comment: C1608X7R1C105K080AC)
C89  ValueDisplayed: 1µF  [0603]  (hidden comment: C1608X7R1C105K080AC)
C90  ValueDisplayed: 0.01µF  [0402_065]  (hidden comment: 520L103KT16T)
C91  ValueDisplayed: 1800pF  [0603]  (hidden comment: GRM1885C1H182JA01D)
C92  ValueDisplayed: 300pF  [0603]  (hidden comment: GRM1885C2A301JA01D)
C93  ValueDisplayed: 0.056µF  [0603]  (hidden comment: GRM188R71H563KA93D)
C94  ValueDisplayed: 0.01µF  [0402_065]  (hidden comment: 520L103KT16T)
C95  ValueDisplayed: 1500pF  [0603]  (hidden comment: GRM1885C1H152JA01J)
C96  ValueDisplayed: 1µF  [0603]  (hidden comment: C1608X7R1C105K080AC)
C97  ValueDisplayed: 0.01µF  [0402_065]  (hidden comment: 520L103KT16T)
C98  ValueDisplayed: 10µF  [0603]  (hidden comment: C1608X5R1A106M080AC)
C99  ValueDisplayed: 1µF  [0603]  (hidden comment: C1608X7R1C105K080AC)
C100  ValueDisplayed: 10µF  [0603]  (hidden comment: C1608X5R1A106M080AC)
C101  ValueDisplayed: 10µF  [0603]  (hidden comment: C1608X5R1A106M080AC)
C102  ValueDisplayed: 10µF  [0603]  (hidden comment: C1608X5R1A106M080AC)
C103  ValueDisplayed: 10µF  [0603]  (hidden comment: C1608X5R1A106M080AC)
C104  ValueDisplayed: 0.1µF  [0603L]  (hidden comment: 0603YC104JAT2A)
C105  ValueDisplayed: 0.1µF  [0603L]  (hidden comment: 0603YC104JAT2A)
C193  ValueDisplayed: 0.1µF  [0603]  (hidden comment: 0603YC104JAT2A)
CE_TP2  5007  [Keystone5007]  (value not drawn)
D6  value Green  [LTST-C191_Green]  (hidden comment: LTST-C191TGKT)
J27  (no value)  [Molex_0853050232]
J28  (no value)  [Molex_0853050232]
L13  ValueDisplayed: 18nH  [IND_LQG15H]  (hidden comment: LQG15HS18NJ02D)
L14  ValueDisplayed: 18nH  [IND_LQG15H]  (hidden comment: LQG15HS18NJ02D)
OSCinM2  142-0701-201  [Johnson_142-0701-20x]
OSCinP2  142-0701-201  [Johnson_142-0701-20x]
R114  ValueDisplayed: 0  [0402]  (hidden comment: CRCW04020000Z0ED)
R115  ValueDisplayed: 50  [0402L]  (hidden comment: FC0402E50R0BST1)
R116  value 0  [0603]  (hidden comment: CRCW06030000Z0EA)
R117  ValueDisplayed: 0  [0402]  (hidden comment: CRCW04020000Z0ED)
R118  value 0  [0603L]  (hidden comment: CRCW06030000Z0EA)
R119  ValueDisplayed: 50  [0402L]  (hidden comment: FC0402E50R0BST1)
R120  value 0  [0603L]  (hidden comment: CRCW06030000Z0EA)
R121  value 0  [0603L]  (hidden comment: CRCW06030000Z0EA)
R122  value 0  [0603]  (hidden comment: CRCW06030000Z0EA)
R123  ValueDisplayed: 100k  [0603]  (hidden comment: CRCW0603100KJNEA)
R124  value 0  [0603]  (hidden comment: CRCW06030000Z0EA)
R125  ValueDisplayed: 0  [0402]  (hidden comment: CRCW04020000Z0ED)
R126  ValueDisplayed: 50  [0402L]  (hidden comment: FC0402E50R0BST1)
R127  ValueDisplayed: 270  [0603]  (hidden comment: RC0603JR-07270RL)
R128  ValueDisplayed: 0  [0603]  (hidden comment: CRCW06030000Z0EA)
R129  ValueDisplayed: 120  [0603]  (hidden comment: CRCW0603120RJNEA)
R130  ValueDisplayed: 50  [0402L]  (hidden comment: FC0402E50R0BST1)
R131  ValueDisplayed: 0  [0402]  (hidden comment: CRCW04020000Z0ED)
R132  ValueDisplayed: 0  [0402]  (hidden comment: CRCW04020000Z0ED)
R135  ValueDisplayed: 100  [0603]  (hidden comment: CRCW0603100RFKEA)
R136  value 330  [0603]  (hidden comment: RC0603JR-07330RL)
R137  ValueDisplayed: 0  [0402]  (hidden comment: CRCW04020000Z0ED)
R138  ValueDisplayed: 51  [0603]  (hidden comment: CRCW060351R0JNEA)
R139  ValueDisplayed: 0  [0603]  (hidden comment: CRCW06030000Z0EA)
R140  ValueDisplayed: 0  [0603]  (hidden comment: CRCW06030000Z0EA)
R141  ValueDisplayed: 0  [0402]  (hidden comment: CRCW04020000Z0ED)
R142  ValueDisplayed: 100  [0603L]  (hidden comment: CRCW0603100RFKEA)
R143  ValueDisplayed: 0  [0402]  (hidden comment: CRCW04020000Z0ED)
R144  ValueDisplayed: 0  [0603]  (hidden comment: CRCW06030000Z0EA)
R145  ValueDisplayed: 0  [0603]  (hidden comment: CRCW06030000Z0EA)
R146  ValueDisplayed: 51  [0603]  (hidden comment: CRCW060351R0JNEA)
R168  ValueDisplayed: 0  [0402]  (hidden comment: CRCW04020000Z0ED)
R215  ValueDisplayed: 10.0k  [0402]  (hidden comment: CRCW040210K0DHEDP)
R216  ValueDisplayed: 10.0k  [0402]  (hidden comment: CRCW040210K0DHEDP)
R277  ValueDisplayed: 0  [0402]  (hidden comment: CRCW04020000Z0ED)
R278  ValueDisplayed: 0  [0402]  (hidden comment: CRCW04020000Z0ED)
R279  ValueDisplayed: 0  [0402]  (hidden comment: CRCW04020000Z0ED)
R280  ValueDisplayed: 0  [0402]  (hidden comment: CRCW04020000Z0ED)
R281  ValueDisplayed: 100  [0402]  (hidden comment: CRCW0402100RJNED)
R300  ValueDisplayed: 0  [0402]  (hidden comment: CRCW04020000Z0ED)
R301  ValueDisplayed: 100  [0402]  (hidden comment: CRCW0402100RJNED)
R352  ValueDisplayed: 0  [0402]  (hidden comment: CRCW04020000Z0ED)
R353  ValueDisplayed: 0  [0402]  (hidden comment: CRCW04020000Z0ED)
R354  ValueDisplayed: 0  [0402]  (hidden comment: CRCW04020000Z0ED)
R355  ValueDisplayed: 0  [0402]  (hidden comment: CRCW04020000Z0ED)
R360  ValueDisplayed: 0  [0402]  (hidden comment: CRCW04020000Z0ED)
R361  ValueDisplayed: 0  [0402]  (hidden comment: CRCW04020000Z0ED)
R364  ValueDisplayed: 0  [0402]  (hidden comment: CRCW04020000Z0ED)
R365  ValueDisplayed: 0  [0402]  (hidden comment: CRCW04020000Z0ED)
RFoutAM2  142-0771-831  [Johnson_142-0771-831]  (value not drawn)
RFoutAP2  142-0771-831  [Johnson_142-0771-831]  (value not drawn)
RFoutBM2  142-0771-831  [Johnson_142-0771-831]  (value not drawn)
RFoutBP2  142-0771-831  [Johnson_142-0771-831]  (value not drawn)
RMPCLK2  5007  [Keystone5007]  (value not drawn)
RMPDIR2  5007  [Keystone5007]  (value not drawn)
U4  LMX2594RHAT  [RHA0040A]
U24  DS90LV028AQMA  [M08A_N]
Vcc_TP2  5007  [Keystone5007]  (value not drawn)
Vtune_TP2  5007  [Keystone5007]  (value not drawn)

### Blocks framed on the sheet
Matched Length: C90 C94 C97 L14 R114 R117 R125 R126 R130 R131 RFoutAM2 RFoutAP2 RFoutBM2 RFoutBP2

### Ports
DCLKout2_LMK_N (in), DCLKout2_LMK_N (out), DCLKout2_LMK_P (in), DCLKout2_LMK_P (out), DCLKout2_N (in), DCLKout2_N* (in), DCLKout2_N* (out), DCLKout2_P (in), DCLKout2_P* (in), DCLKout2_P* (out), LMK_LMX_CLK (in), LMK_LMX_DATA (in), LMX2_CSb (in), LMX2_REFN (in), LMX2_REFP (in), LMX2_SDO (out), LMX2_SYNC (in), LMX2_SYNC (out), LMX2_SYSREFREQ (in), LMX2_SYSREFREQ (out), SDCLKout3_LMK_N (in), SDCLKout3_LMK_N (out), SDCLKout3_LMK_P (in), SDCLKout3_LMK_P (out), SDCLKout3_N (in), SDCLKout3_P (in), SDCLKout5_N (in), SDCLKout5_P (in)

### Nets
+3.3V_LMX: C84.2 C85.2 C86.2 C87.2 R116.1 R118.1 R121.1 R122.2 R123.1 R124.2 Vcc_TP2.1
+3.3V_LMXRF: L13.1 L14.1 R120.1
+3.3VLMK: C193.2 U24.8(VCC)
GND: C78.1 C79.1 C80.1 C82.2 C83.1 C84.1 C85.1 C86.1 C87.1 C88.1 C89.1 C91.1 C92.2 C94.1 C95.2 C96.1 C98.2 C99.1 C100.2 C101.2 C102.1 C103.1 C193.1 D6.2(K) J27.2 J28.2 OSCinM2.2 OSCinM2.3 OSCinM2.4 OSCinM2.5 OSCinP2.2 OSCinP2.3 OSCinP2.4 OSCinP2.5 R129.2 R138.2 R146.1 R215.2 R216.2 RFoutAM2.2 RFoutAM2.3 RFoutAM2.4 RFoutAP2.2 RFoutAP2.3 RFoutAP2.4 RFoutBM2.2 RFoutBM2.3 RFoutBM2.4 RFoutBP2.2 RFoutBP2.3 RFoutBP2.4 U4.2(GND) U4.4(GND) U4.6(GND) U4.13(GND) U4.14(GND) U4.25(GND) U4.31(GND) U4.34(GND) U4.39(GND) U4.40(GND) U4.41(GND) U24.5(GND)
MUXout2: R135.1 R136.2 U4.20(MUXOUT)
ADC_CLK2+: C77.2 R115.1 U4.23(RFOUTAP)
ADC_CLK2-: C81.2 R119.1 U4.22(RFOUTAM)
ADC_SYSREF2+: C90.2 R126.2 U4.18(RFOUTBP/SYSREFOUTP)
ADC_SYSREF2-: C97.2 R130.1 U4.19(RFOUTBM/SYSREFOUTN)
DCLKout2_LMK_N: R117.2 R365.1 ; port DCLKout2_LMK_N
DCLKout2_LMK_P: R114.2 R364.1 ; port DCLKout2_LMK_P
DCLKout2_N: R279.2 R365.2 ; port DCLKout2_N
DCLKout2_N*: R143.1 R279.1 ; port DCLKout2_N*
DCLKout2_P: R278.2 R364.2 ; port DCLKout2_P
DCLKout2_P*: R141.1 R278.1 ; port DCLKout2_P*
LMK_LMX_CLK: U4.16(SCK) ; port LMK_LMX_CLK
LMK_LMX_DATA: U4.17(SDI) ; port LMK_LMX_DATA
LMX2_CSb: U4.24(CSB) ; port LMX2_CSb
LMX2_REFN: R168.1 ; port LMX2_REFN
LMX2_REFP: R137.2 ; port LMX2_REFP
LMX2_SDO: R135.2 ; port LMX2_SDO
LMX2_SYNC: R277.2 R280.1 U24.7(ROUT1) ; port LMX2_SYNC
LMX2_SYSREFREQ: R132.2 R300.2 U24.6(ROUT2) ; port LMX2_SYSREFREQ
LMX_OSCin2+: C104.2 U4.8(OSCINP)
LMX_OSCin2-: C105.2 U4.9(OSCINM)
RFoutAM2: C81.1 R117.1 RFoutAM2.1
RFoutAP2: C77.1 R114.1 RFoutAP2.1
RFoutBM2: C90.1 R125.1 RFoutBM2.1
RFoutBP2: C97.1 R131.1 RFoutBP2.1
SDCLKout3_LMK_N: R131.2 R360.1 ; port SDCLKout3_LMK_N
SDCLKout3_LMK_P: R125.2 R361.1 ; port SDCLKout3_LMK_P
SDCLKout3_N: R354.1 R360.2 ; port SDCLKout3_N
SDCLKout3_P: R355.1 R361.2 ; port SDCLKout3_P
SDCLKout5_N: R281.1 U24.1(RIN1-) ; port SDCLKout5_N
SDCLKout5_P: R280.2 R281.2 U24.2(RIN1+) ; port SDCLKout5_P
NetC78_2: C78.2 L13.2 R115.2 R119.2
NetC79_2: C79.2 R116.2 U4.7(VCCDIG)
NetC80_2: C80.2 R118.2 U4.11(VCCCP)
NetC82_1: C82.1 R121.2 U4.15(VCCMASH)
NetC83_2: C83.2 R120.2 U4.21(VCCBUF)
NetC88_2: C88.2 R122.1 U4.26(VCCVCO2)
NetC89_2: C89.2 R124.1 U4.37(VCCVCO)
NetC91_2: C91.2 R127.1 U4.35(VTUNE)
NetC92_1: C92.1 R127.2 R128.2 Vtune_TP2.1
NetC93_1: C93.1 C95.1 R128.1 U4.12(CPOUT)
NetC93_2: C93.2 R129.1
NetC94_2: C94.2 L14.2 R126.1 R130.2
NetC96_2: C96.2 U4.10(VREGIN)
NetC98_1: C98.1 U4.36(VREFVCO)
NetC99_2: C99.2 U4.38(VREGVCO)
NetC100_1: C100.1 U4.29(VREFVCO2)
NetC101_1: C101.1 U4.3(VBIASVCO)
NetC102_2: C102.2 U4.27(VBIASVCO2)
NetC103_2: C103.2 U4.33(VBIASVARAC)
NetC104_1: C104.1 R140.2 R142.2
NetC105_1: C105.1 R142.1 R145.1
NetCE_TP2_1: CE_TP2.1 R123.2 U4.1(CE)
NetD6_1: D6.1(A) R136.1
NetJ27_1: J27.1 R353.2
NetJ28_1: J28.1 R352.2
NetOSCinM2_1: OSCinM2.1 R144.1
NetOSCinP2_1: OSCinP2.1 R139.1
NetR132_1: R132.1 R216.1 R353.1 U4.28(SYSREFREQ)
NetR137_1: R137.1 R138.1 R139.2 R140.1 R141.2
NetR143_2: R143.2 R144.2 R145.2 R146.2 R168.2
NetR215_1: R215.1 R277.1 R352.1 U4.5(SYNC)
NetR300_1: R300.1 R301.1 R354.2 U24.3(RIN2+)
NetR301_2: R301.2 R355.2 U24.4(RIN2-)
NetRMPCLK2_1: RMPCLK2.1 U4.30(RAMPCLK/TRIG1)
NetRMPDIR2_1: RMPDIR2.1 U4.32(RAMPDIR/TRIG2)

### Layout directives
differential pair: DCLKout2_LMK_N, DCLKout2_LMK_P

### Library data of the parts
C77 C78 C81 C90 C94 C97 = 520L103KT16T: as C44 on sheet TIDA-010131-E3_LMX2594R_1
C79 C88 C89 = C1608X7R1C105K080AC: as C46 on sheet TIDA-010131-E3_LMX2594R_1
C80 C82 = C1608X7R1C105K080AC: as C47 on sheet TIDA-010131-E3_LMX2594R_1
C83 C104 C105 = 0603YC104JAT2A: as C50 on sheet TIDA-010131-E3_LMX2594R_1
C84 C87 C193 = 0603YC104JAT2A: as C51 on sheet TIDA-010131-E3_LMX2594R_1
C85 C86 = C0805C106K8PACTU: as C52 on sheet TIDA-010131-E3_LMX2594R_1
C91 = GRM1885C1H182JA01D: as C58 on sheet TIDA-010131-E3_LMX2594R_1
C92 = GRM1885C2A301JA01D: as C59 on sheet TIDA-010131-E3_LMX2594R_1
C93 = GRM188R71H563KA93D: as C60 on sheet TIDA-010131-E3_LMX2594R_1
C95 = GRM1885C1H152JA01J: as C62 on sheet TIDA-010131-E3_LMX2594R_1
C96 = C1608X7R1C105K080AC: as C63 on sheet TIDA-010131-E3_LMX2594R_1
C98 C100-C103 = C1608X5R1A106M080AC: as C65 on sheet TIDA-010131-E3_LMX2594R_1
C99 = C1608X7R1C105K080AC: as C66 on sheet TIDA-010131-E3_LMX2594R_1
CE_TP2 RMPCLK2 RMPDIR2 Vcc_TP2 Vtune_TP2 = 5007: as CE_TP1 on sheet TIDA-010131-E3_LMX2594R_1
D6 = LTST-C191TGKT: as D5 on sheet TIDA-010131-E3_LMX2594R_1
J27 J28 = CMP-0077224-1: as J18 on sheet TIDA-010131-E3_LMX2594R_1
L13 L14 = LQG15HS18NJ02D: as L11 on sheet TIDA-010131-E3_LMX2594R_1
OSCinM2 OSCinP2 = 142-0701-201: as OSCinM1 on sheet TIDA-010131-E3_LMX2594R_1
R114 R117 R125 R131 R132 R141 R143 R277-R280 R300 R352-R355 R360 R361 R364 R365 = CRCW04020000Z0ED: as R81 on sheet TIDA-010131-E3_LMX2594R_1
R115 R119 R126 R130 = FC0402E50R0BST1: as R82 on sheet TIDA-010131-E3_LMX2594R_1
R116 R118 R120-R122 R124 = CRCW06030000Z0EA: as R83 on sheet TIDA-010131-E3_LMX2594R_1
R123 = CRCW0603100KJNEA: as R90 on sheet TIDA-010131-E3_LMX2594R_1
R127 = RC0603JR-07270RL: as R94 on sheet TIDA-010131-E3_LMX2594R_1
R128 R139 R140 R144 R145 = CRCW06030000Z0EA: as R95 on sheet TIDA-010131-E3_LMX2594R_1
R129 = CRCW0603120RJNEA: as R96 on sheet TIDA-010131-E3_LMX2594R_1
R135 = CRCW0603100RFKEA: as R102 on sheet TIDA-010131-E3_LMX2594R_1
R136 = RC0603JR-07330RL: as R105 on sheet TIDA-010131-E3_LMX2594R_1
R137 R168 = CRCW04020000Z0ED: as R103 on sheet TIDA-010131-E3_LMX2594R_1
R138 R146 = CRCW060351R0JNEA: as R104 on sheet TIDA-010131-E3_LMX2594R_1
R142 = CRCW0603100RFKEA: as R109 on sheet TIDA-010131-E3_LMX2594R_1
R215 R216 = CRCW040210K0DHEDP: as R213 on sheet TIDA-010131-E3_LMX2594R_1
R281 R301 = CRCW0402100RJNED: as R133 on sheet TIDA-010131-E3_LMX2594R_1
RFoutAM2 RFoutAP2 RFoutBM2 RFoutBP2 = 142-0771-831: as RFoutAM1 on sheet TIDA-010131-E3_LMX2594R_1
U4 = LMX2594RHAR: as U3 on sheet TIDA-010131-E3_LMX2594R_1
U24 = DS90LV028AQMA: as U23 on sheet TIDA-010131-E3_LMX2594R_1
